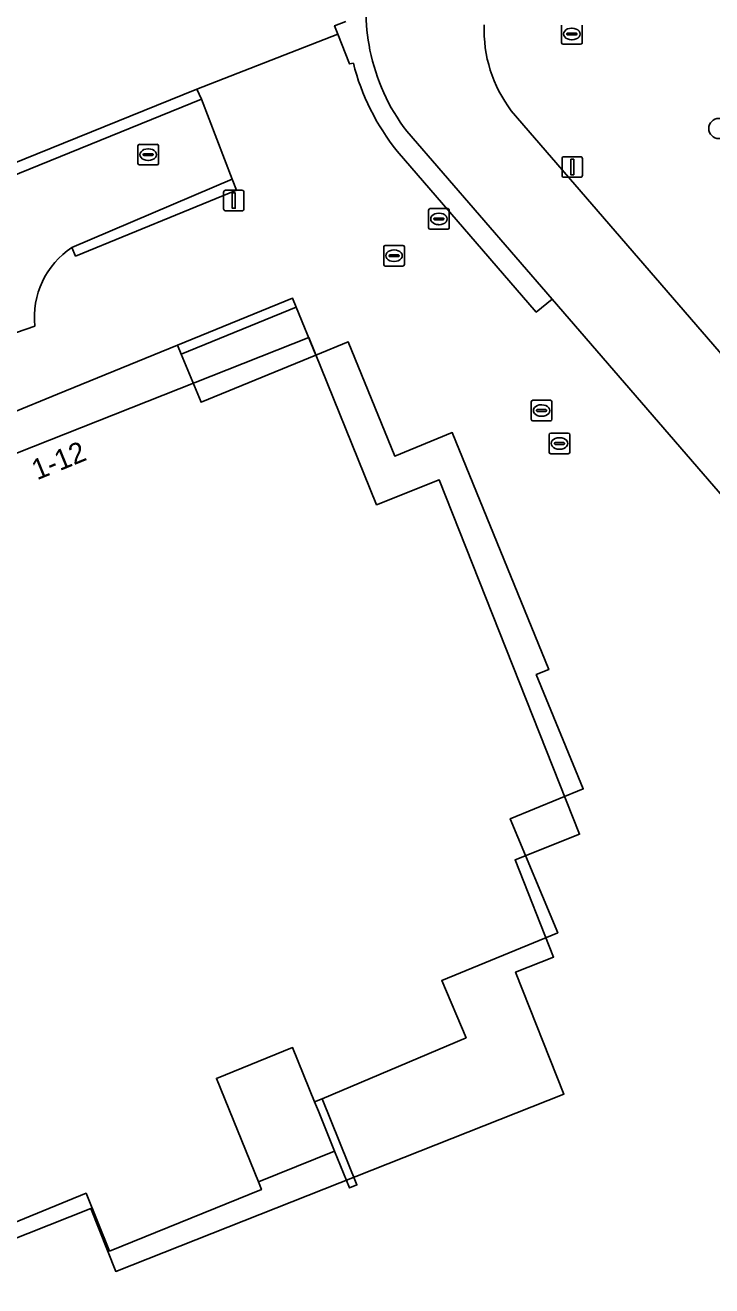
# Model space of a CAD drawing. Extents: x 156661 to 157576, y 383570 to 384425.
# Drawn here: x 156796.6 to 156830, y 383820 to 383881.2 of the extents above; entities that cross this region are included whole.
import ezdxf

# ---------------------------------------------------------------- set-up
doc = ezdxf.new("R2010")
doc.units = 0
for name, color, linetype in [('IMGEO_Berm_open', 7, 'Continuous'), ('IMGEO_Boom', 7, 'Continuous'), ('IMGEO_Groenvoorziening', 7, 'Continuous'), ('IMGEO_Lichtmast', 7, 'Continuous'), ('IMGEO_Muur', 7, 'Continuous'), ('IMGEO_Pand', 7, 'Continuous'), ('IMGEO_Pand_nummerreeks', 7, 'Continuous'), ('IMGEO_Pand_vergunning_verleend', 7, 'Continuous'), ('IMGEO_Rijbaan_lokaal_gesloten', 7, 'Continuous'), ('IMGEO_Rijbaan_lokaal_open', 7, 'Continuous'), ('IMGEO_Rioolput', 7, 'Continuous'), ('IMGEO_Voetpad_op_trap', 7, 'Continuous')]:
    doc.layers.add(name, color=color, linetype=linetype)

msp = doc.modelspace()

# ---------------------------------------------------------------- linework, layer by layer
at = {"layer": 'IMGEO_Berm_open'}
for points in [[(156812.204, 383881.419), (156811.669, 383881.211), (156811.831, 383880.795), (156812.391, 383879.356), (156812.577, 383879.388)], [(156814.702, 383875.125), (156821.46, 383867.3), (156822.231, 383867.92), (156815.167, 383876.091)]]:
    msp.add_lwpolyline(points, dxfattribs=at)
for centre, radius, start, end in [((156822.961, 383881.977), 9.772, 179.98469, 191.49468), ((156822.9, 383881.962), 9.71, 191.47815, 217.20576), ((156823.408, 383882.126), 11.171, 194.18553, 218.80471)]:
    msp.add_arc(centre, radius, start, end, dxfattribs=at)
at = {"layer": 'IMGEO_Boom'}
msp.add_circle((156830.325, 383876.218), 0.489, dxfattribs=at)
at = {"layer": 'IMGEO_Groenvoorziening'}
for points in [[(156774.705, 383865.868), (156804.978, 383878.126), (156811.831, 383880.795), (156811.669, 383881.211), (156812.204, 383881.419)], [(156812.577, 383879.388), (156812.391, 383879.356), (156811.831, 383880.795), (156804.978, 383878.126), (156805.203, 383877.639), (156806.698, 383873.755), (156806.905, 383873.221), (156799.086, 383870.018), (156798.908, 383870.442)], [(156820.249, 383877.085), (156862.917, 383827.693), (156866.643, 383823.379), (156904.906, 383779.134), (156906.372, 383777.464), (156907.586, 383778.508), (156909.46, 383776.346)], [(156863.331, 383820.379), (156859.631, 383824.659), (156822.231, 383867.92), (156821.46, 383867.3), (156814.702, 383875.125)], [(156795.923, 383862.376), (156798.209, 383863.311), (156804.039, 383865.696), (156809.615, 383867.977), (156809.794, 383867.543), (156810.752, 383865.212), (156812.318, 383865.856), (156814.59, 383860.304), (156817.377, 383861.45), (156822.064, 383849.936), (156821.462, 383849.689), (156823.742, 383844.139), (156820.198, 383842.684), (156822.503, 383837.144), (156816.871, 383834.832), (156818.054, 383832.045), (156811.056, 383829.074), (156812.748, 383824.896), (156812.387, 383824.749), (156811.662, 383826.538), (156807.966, 383825.04), (156808.116, 383824.67), (156800.741, 383821.682), (156799.598, 383824.496), (156795.415, 383822.785)], [(156797.106, 383866.622), (156792.449, 383865.012)]]:
    msp.add_lwpolyline(points, dxfattribs=at)
for centre, radius, start, end in [((156825.375, 383880.993), 6.446, 177.63967, 217.31682), ((156823.408, 383882.126), 11.171, 194.18553, 218.80471), ((156801.172, 383867.039), 4.087, 123.63597, 185.85492)]:
    msp.add_arc(centre, radius, start, end, dxfattribs=at)
at = {"layer": 'IMGEO_Lichtmast'}
for p, q in [((156822.711, 383873.948), (156822.711, 383874.748)), ((156822.711, 383874.748), (156822.711, 383873.948)), ((156822.811, 383874.848), (156823.601, 383874.848)), ((156823.601, 383874.848), (156822.811, 383874.848)), ((156823.701, 383874.748), (156823.701, 383873.948)), ((156823.701, 383873.948), (156823.701, 383874.748)), ((156823.601, 383873.848), (156822.811, 383873.848)), ((156822.811, 383873.848), (156823.601, 383873.848)), ((156806.274, 383872.317), (156806.274, 383873.117)), ((156806.274, 383873.117), (156806.274, 383872.317)), ((156806.374, 383873.217), (156807.164, 383873.217)), ((156807.164, 383873.217), (156806.374, 383873.217)), ((156807.264, 383873.117), (156807.264, 383872.317)), ((156807.264, 383872.317), (156807.264, 383873.117)), ((156807.164, 383872.217), (156806.374, 383872.217)), ((156806.374, 383872.217), (156807.164, 383872.217))]:
    msp.add_line(p, q, dxfattribs=at)
for points in [[(156823.131, 383874.723), (156823.281, 383874.723), (156823.281, 383873.973), (156823.131, 383873.973), (156823.131, 383874.723)], [(156806.694, 383873.092), (156806.844, 383873.092), (156806.844, 383872.342), (156806.694, 383872.342), (156806.694, 383873.092)]]:
    msp.add_lwpolyline(points, dxfattribs=at)
for centre, start, end in [((156822.811, 383874.748), 90, 180), ((156822.811, 383874.748), 90, 180), ((156823.601, 383874.748), 0, 90), ((156823.601, 383874.748), 360, 90), ((156822.811, 383873.948), 180, 270), ((156822.811, 383873.948), 180, 270), ((156823.601, 383873.948), 270, 0), ((156823.601, 383873.948), 270, 0), ((156806.374, 383873.117), 90, 180), ((156806.374, 383873.117), 90, 180), ((156807.164, 383873.117), 0, 90), ((156807.164, 383873.117), 360, 90), ((156806.374, 383872.317), 180, 270), ((156806.374, 383872.317), 180, 270), ((156807.164, 383872.317), 270, 0), ((156807.164, 383872.317), 270, 0)]:
    msp.add_arc(centre, 0.1, start, end, dxfattribs=at)
at = {"layer": 'IMGEO_Muur'}
for points in [[(156809.794, 383867.543), (156809.615, 383867.977), (156804.039, 383865.696), (156804.217, 383865.261)], [(156811.056, 383829.074), (156810.694, 383828.927), (156810.877, 383828.476), (156811.662, 383826.538), (156812.387, 383824.749), (156812.748, 383824.896)]]:
    msp.add_lwpolyline(points, close=True, dxfattribs=at)
at = {"layer": 'IMGEO_Pand'}
msp.add_lwpolyline([(156795.415, 383822.785), (156799.598, 383824.496), (156800.741, 383821.682), (156808.116, 383824.67), (156807.966, 383825.04), (156805.926, 383830.075), (156809.623, 383831.572), (156810.694, 383828.927), (156811.056, 383829.074), (156818.054, 383832.045), (156816.871, 383834.832), (156822.503, 383837.144), (156820.198, 383842.684), (156823.742, 383844.139), (156821.462, 383849.689), (156822.064, 383849.936), (156817.377, 383861.45), (156814.59, 383860.304), (156812.318, 383865.856), (156810.752, 383865.212), (156805.179, 383862.921), (156804.217, 383865.261), (156804.039, 383865.696), (156798.209, 383863.311), (156795.923, 383862.376)], dxfattribs=at)
at = {"layer": 'IMGEO_Pand_vergunning_verleend'}
msp.add_lwpolyline([(156780.469, 383854.207), (156810.422, 383866.069), (156813.706, 383857.943), (156816.747, 383859.147), (156823.563, 383841.936), (156820.432, 383840.696), (156822.305, 383835.967), (156820.454, 383835.234), (156822.799, 383829.314), (156801.042, 383820.698), (156799.834, 383823.747), (156795.744, 383822.127), (156793.475, 383827.857), (156790.011, 383826.485), (156783.663, 383842.517), (156784.904, 383843.008)], close=True, dxfattribs=at)
at = {"layer": 'IMGEO_Rijbaan_lokaal_gesloten'}
for points in [[(156805.203, 383877.639), (156804.978, 383878.126), (156774.705, 383865.868)], [(156774.773, 383865.272), (156805.203, 383877.639)]]:
    msp.add_lwpolyline(points, dxfattribs=at)
msp.add_lwpolyline([(156806.698, 383873.755), (156798.908, 383870.442), (156799.086, 383870.018), (156806.905, 383873.221)], close=True, dxfattribs=at)
at = {"layer": 'IMGEO_Rijbaan_lokaal_open'}
for points in [[(156798.908, 383870.442), (156806.698, 383873.755), (156805.203, 383877.639), (156774.773, 383865.272)], [(156908.893, 383774.52), (156906.372, 383777.464), (156904.906, 383779.134), (156866.643, 383823.379), (156862.917, 383827.693), (156820.249, 383877.085)], [(156815.167, 383876.091), (156822.231, 383867.92), (156859.631, 383824.659), (156863.331, 383820.379), (156901.778, 383775.877), (156902.832, 383774.643), (156904.727, 383772.433)], [(156792.449, 383865.012), (156797.106, 383866.622)]]:
    msp.add_lwpolyline(points, dxfattribs=at)
for centre, radius, start, end in [((156822.961, 383881.977), 9.772, 179.98469, 191.49468), ((156825.375, 383880.993), 6.446, 177.63967, 217.31682), ((156822.9, 383881.962), 9.71, 191.47815, 217.20576), ((156801.172, 383867.039), 4.087, 123.63597, 185.85492)]:
    msp.add_arc(centre, radius, start, end, dxfattribs=at)
at = {"layer": 'IMGEO_Rioolput'}
for p, q in [((156822.689, 383880.385), (156822.689, 383881.237)), ((156823.177, 383881.091), (156823.202, 383881.091)), ((156823.69, 383881.237), (156823.69, 383880.385)), ((156822.948, 383880.805), (156822.948, 383880.817)), ((156823.386, 383880.768), (156822.988, 383880.768)), ((156822.991, 383880.854), (156823.389, 383880.854)), ((156823.2, 383880.531), (156823.175, 383880.531)), ((156823.432, 383880.817), (156823.432, 383880.805)), ((156823.616, 383880.311), (156822.764, 383880.311)), ((156802.115, 383874.524), (156802.115, 383875.376)), ((156802.19, 383875.45), (156803.042, 383875.45)), ((156802.374, 383874.944), (156802.374, 383874.956)), ((156802.812, 383874.907), (156802.414, 383874.907)), ((156802.417, 383874.993), (156802.815, 383874.993)), ((156802.603, 383875.23), (156802.628, 383875.23)), ((156802.858, 383874.956), (156802.858, 383874.944)), ((156803.116, 383875.376), (156803.116, 383874.524)), ((156803.042, 383874.45), (156802.19, 383874.45)), ((156802.626, 383874.67), (156802.601, 383874.67)), ((156816.233, 383871.401), (156816.233, 383872.253)), ((156816.308, 383872.327), (156817.16, 383872.327)), ((156816.535, 383871.87), (156816.933, 383871.87)), ((156816.721, 383872.107), (156816.746, 383872.107)), ((156817.234, 383872.253), (156817.234, 383871.401)), ((156817.16, 383871.327), (156816.308, 383871.327)), ((156816.492, 383871.821), (156816.492, 383871.833)), ((156816.93, 383871.784), (156816.532, 383871.784)), ((156816.744, 383871.547), (156816.719, 383871.547)), ((156816.976, 383871.833), (156816.976, 383871.821)), ((156814.052, 383869.613), (156814.052, 383870.465)), ((156814.127, 383870.539), (156814.979, 383870.539)), ((156814.311, 383870.033), (156814.311, 383870.045)), ((156814.354, 383870.082), (156814.752, 383870.082)), ((156814.54, 383870.319), (156814.565, 383870.319)), ((156814.795, 383870.045), (156814.795, 383870.033)), ((156815.053, 383870.465), (156815.053, 383869.613)), ((156814.979, 383869.539), (156814.127, 383869.539)), ((156814.749, 383869.996), (156814.351, 383869.996)), ((156814.563, 383869.759), (156814.538, 383869.759)), ((156821.219, 383862.091), (156821.219, 383862.943)), ((156821.294, 383863.017), (156822.146, 383863.017)), ((156821.707, 383862.797), (156821.732, 383862.797)), ((156822.22, 383862.943), (156822.22, 383862.091)), ((156821.478, 383862.511), (156821.478, 383862.523)), ((156821.916, 383862.474), (156821.518, 383862.474)), ((156821.521, 383862.56), (156821.919, 383862.56)), ((156821.73, 383862.237), (156821.705, 383862.237)), ((156821.962, 383862.523), (156821.962, 383862.511)), ((156822.146, 383862.017), (156821.294, 383862.017)), ((156822.087, 383860.492), (156822.087, 383861.344)), ((156822.162, 383861.418), (156823.014, 383861.418)), ((156822.346, 383860.912), (156822.346, 383860.924)), ((156822.784, 383860.875), (156822.386, 383860.875)), ((156822.389, 383860.961), (156822.787, 383860.961)), ((156822.575, 383861.198), (156822.6, 383861.198)), ((156822.83, 383860.924), (156822.83, 383860.912)), ((156823.088, 383861.344), (156823.088, 383860.492)), ((156823.014, 383860.418), (156822.162, 383860.418)), ((156822.598, 383860.638), (156822.573, 383860.638))]:
    msp.add_line(p, q, dxfattribs=at)
for points in [[(156822.689, 383880.385), (156822.689, 383881.237)], [(156823.69, 383881.237), (156823.69, 383880.385)], [(156823.616, 383880.311), (156822.764, 383880.311)], [(156802.115, 383874.524), (156802.115, 383875.376)], [(156802.19, 383875.45), (156803.042, 383875.45)], [(156803.116, 383875.376), (156803.116, 383874.524)], [(156803.042, 383874.45), (156802.19, 383874.45)], [(156816.233, 383871.401), (156816.233, 383872.253)], [(156816.308, 383872.327), (156817.16, 383872.327)], [(156817.234, 383872.253), (156817.234, 383871.401)], [(156817.16, 383871.327), (156816.308, 383871.327)], [(156814.052, 383869.613), (156814.052, 383870.465)], [(156814.127, 383870.539), (156814.979, 383870.539)], [(156815.053, 383870.465), (156815.053, 383869.613)], [(156814.979, 383869.539), (156814.127, 383869.539)], [(156821.219, 383862.091), (156821.219, 383862.943)], [(156821.294, 383863.017), (156822.146, 383863.017)], [(156822.22, 383862.943), (156822.22, 383862.091)], [(156822.146, 383862.017), (156821.294, 383862.017)], [(156822.087, 383860.492), (156822.087, 383861.344)], [(156822.162, 383861.418), (156823.014, 383861.418)], [(156823.088, 383861.344), (156823.088, 383860.492)], [(156823.014, 383860.418), (156822.162, 383860.418)]]:
    msp.add_lwpolyline(points, dxfattribs=at)
for centre, radius, start, end in [((156822.988, 383880.814), 0.0403, 85.87752, 175.75265), ((156822.985, 383880.804), 0.0366, 178.93798, 274.71019), ((156823.389, 383880.811), 0.043, 264.86636, 352.45326), ((156823.393, 383880.816), 0.0386, 1.73085, 96.63898), ((156822.766, 383880.387), 0.0765, 181.55205, 268.44795), ((156822.766, 383880.387), 0.0765, 181.55205, 268.44795), ((156823.614, 383880.387), 0.0765, 271.55205, 358.44795), ((156823.614, 383880.387), 0.0765, 271.55205, 358.44795), ((156802.192, 383875.374), 0.0765, 91.55205, 178.44795), ((156802.192, 383875.374), 0.0765, 91.55205, 178.44795), ((156802.414, 383874.953), 0.0403, 85.87752, 175.75265), ((156802.411, 383874.943), 0.0366, 178.93798, 274.71019), ((156802.815, 383874.95), 0.043, 264.86636, 352.45326), ((156802.819, 383874.955), 0.0386, 1.73085, 96.63898), ((156803.04, 383875.374), 0.0765, 1.55205, 88.44795), ((156803.04, 383875.374), 0.0765, 1.55205, 88.44795), ((156802.192, 383874.526), 0.0765, 181.55205, 268.44795), ((156802.192, 383874.526), 0.0765, 181.55205, 268.44795), ((156803.04, 383874.526), 0.0765, 271.55205, 358.44795), ((156803.04, 383874.526), 0.0765, 271.55205, 358.44795), ((156816.31, 383872.251), 0.0765, 91.55205, 178.44795), ((156816.31, 383872.251), 0.0765, 91.55205, 178.44795), ((156816.532, 383871.83), 0.0403, 85.87752, 175.75265), ((156816.937, 383871.832), 0.0386, 1.73085, 96.63898), ((156817.158, 383872.251), 0.0765, 1.55205, 88.44795), ((156817.158, 383872.251), 0.0765, 1.55205, 88.44795), ((156816.31, 383871.403), 0.0765, 181.55205, 268.44795), ((156816.31, 383871.403), 0.0765, 181.55205, 268.44795), ((156816.529, 383871.82), 0.0366, 178.93798, 274.71019), ((156816.933, 383871.827), 0.043, 264.86636, 352.45326), ((156817.158, 383871.403), 0.0765, 271.55205, 358.44795), ((156817.158, 383871.403), 0.0765, 271.55205, 358.44795), ((156814.129, 383870.463), 0.0765, 91.55205, 178.44795), ((156814.129, 383870.463), 0.0765, 91.55205, 178.44795), ((156814.351, 383870.042), 0.0403, 85.87752, 175.75265), ((156814.348, 383870.032), 0.0366, 178.93798, 274.71019), ((156814.752, 383870.039), 0.043, 264.86636, 352.45326), ((156814.756, 383870.044), 0.0386, 1.73085, 96.63898), ((156814.977, 383870.463), 0.0765, 1.55205, 88.44795), ((156814.977, 383870.463), 0.0765, 1.55205, 88.44795), ((156814.129, 383869.615), 0.0765, 181.55205, 268.44795), ((156814.129, 383869.615), 0.0765, 181.55205, 268.44795), ((156814.977, 383869.615), 0.0765, 271.55205, 358.44795), ((156814.977, 383869.615), 0.0765, 271.55205, 358.44795), ((156821.296, 383862.941), 0.0765, 91.55205, 178.44795), ((156821.296, 383862.941), 0.0765, 91.55205, 178.44795), ((156822.144, 383862.941), 0.0765, 1.55205, 88.44795), ((156822.144, 383862.941), 0.0765, 1.55205, 88.44795), ((156821.296, 383862.093), 0.0765, 181.55205, 268.44795), ((156821.296, 383862.093), 0.0765, 181.55205, 268.44795), ((156821.518, 383862.52), 0.0403, 85.87752, 175.75265), ((156821.515, 383862.51), 0.0366, 178.93798, 274.71019), ((156821.919, 383862.517), 0.043, 264.86636, 352.45326), ((156821.923, 383862.522), 0.0386, 1.73085, 96.63898), ((156822.144, 383862.093), 0.0765, 271.55205, 358.44795), ((156822.144, 383862.093), 0.0765, 271.55205, 358.44795), ((156822.164, 383861.342), 0.0765, 91.55205, 178.44795), ((156822.164, 383861.342), 0.0765, 91.55205, 178.44795), ((156822.386, 383860.921), 0.0403, 85.87752, 175.75265), ((156822.383, 383860.911), 0.0366, 178.93798, 274.71019), ((156822.787, 383860.918), 0.043, 264.86636, 352.45326), ((156822.791, 383860.923), 0.0386, 1.73085, 96.63898), ((156823.012, 383861.342), 0.0765, 1.55205, 88.44795), ((156823.012, 383861.342), 0.0765, 1.55205, 88.44795), ((156822.164, 383860.494), 0.0765, 181.55205, 268.44795), ((156822.164, 383860.494), 0.0765, 181.55205, 268.44795), ((156823.012, 383860.494), 0.0765, 271.55205, 358.44795), ((156823.012, 383860.494), 0.0765, 271.55205, 358.44795)]:
    msp.add_arc(centre, radius, start, end, dxfattribs=at)
for centre, major_axis, ratio, start_param, end_param in [((156823.176, 383880.811), (-0.387, 0.002), 0.722429, 4.712389, 7.853982), ((156823.201, 383880.811), (-0.39, 0.002), 0.717154, 1.570796, 4.712389), ((156802.602, 383874.95), (-0.387, 0.002), 0.722429, 4.712389, 7.853982), ((156802.627, 383874.95), (-0.39, 0.002), 0.717154, 1.570796, 4.712389), ((156816.72, 383871.827), (-0.387, 0.002), 0.722429, 4.712389, 7.853982), ((156816.745, 383871.827), (-0.39, 0.002), 0.717154, 1.570796, 4.712389), ((156814.539, 383870.039), (-0.387, 0.002), 0.722429, 4.712389, 7.853982), ((156814.564, 383870.039), (-0.39, 0.002), 0.717154, 1.570796, 4.712389), ((156821.706, 383862.517), (-0.387, 0.002), 0.722429, 4.712389, 7.853982), ((156821.731, 383862.517), (-0.39, 0.002), 0.717154, 1.570796, 4.712389), ((156822.574, 383860.918), (-0.387, 0.002), 0.722429, 4.712389, 7.853982), ((156822.599, 383860.918), (-0.39, 0.002), 0.717154, 1.570796, 4.712389)]:
    msp.add_ellipse(centre, major_axis=major_axis, ratio=ratio, start_param=start_param, end_param=end_param, dxfattribs=at)
at = {"layer": 'IMGEO_Voetpad_op_trap'}
for points in [[(156810.752, 383865.212), (156809.794, 383867.543), (156804.217, 383865.261), (156805.179, 383862.921)], [(156810.694, 383828.927), (156809.623, 383831.572), (156805.926, 383830.075), (156807.966, 383825.04), (156811.662, 383826.538), (156810.877, 383828.476)]]:
    msp.add_lwpolyline(points, close=True, dxfattribs=at)

# ---------------------------------------------------------------- texts
at = {"layer": 'IMGEO_Pand_nummerreeks'}
msp.add_text('1-12', height=1, rotation=22.25368, dxfattribs=at).set_placement((156797.216, 383859.123))

doc.saveas('drawing.dxf')
